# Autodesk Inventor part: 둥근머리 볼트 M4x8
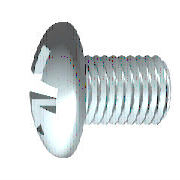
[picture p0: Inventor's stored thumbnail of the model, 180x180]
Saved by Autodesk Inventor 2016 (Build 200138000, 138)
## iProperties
Created: 2012-02
Part Number: 둥근머리 볼트 M4x8
Material: 강철, 연강
Description: 십자 오목 머리 나사
Document SubType Name: Modeling
Standard: KS B 1023
Designer: mduedu
Standards Organization: KS
Language: ko-KR
Size Designation: A  M 4 x 8 - H
Categories: <MemberInstance><Categories><Category DisplayName="조임쇠" InternalName="e4da775c-781d-43d5-af7c-5136215cf5a6" Mnemonic="FSTN"><Category DisplayName="볼트" InternalN
Density: 1 g/cm^3
Appearance: 노란색
IsCustomPart: 1
Author: mduedu
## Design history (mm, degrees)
body "Solid1"
workplane "Work Plane3"
sketch "스케치2"
  geometry: L1 (-5.374, 0)-(5.374, 0) reference; L2 (0, -5.374)-(0, 5.374) reference; L3 (0, 2.3)-(0, 0); L4 (0, 0)-(2.3, 0); L5 (0, 0)-(2.714, 2.714); L6 (0.311, 2.279)-(0.392, 0.703); L7 (2.279, 0.311)-(0.703, 0.392); L8 (0.311, -2.279)-(0.392, -0.703); L9 (2.279, -0.311)-(0.703, -0.392); L10 (-0.311, 2.279)-(-0.392, 0.703); L11 (-2.279, 0.311)-(-0.703, 0.392); L12 (-2.279, -0.311)-(-0.703, -0.392); L13 (-0.311, -2.279)-(-0.392, -0.703); A1 r 0.69 centre (0, 0) between (0.69, 0) and (0, 0.69); A2 r 2.3 centre (0, 0) between (2.3, 0) and (2.279, 0.311); A3 r 2.3 centre (0, 0) between (0.311, 2.279) and (0, 2.3); A4 r 2.3 centre (0, 0) between (2.279, 0.311) and (0.311, 2.279); A5 r 2.3 centre (0, 0) between (0, -2.3) and (0.311, -2.279); A6 r 2.3 centre (0, 0) between (0.311, -2.279) and (2.279, -0.311); A7 r 2.3 centre (0, 0) between (2.279, -0.311) and (2.3, 0); A8 r 2.3 centre (0, 0) between (-2.279, 0.311) and (-2.3, 0); A9 r 2.3 centre (0, 0) between (-0.311, 2.279) and (-2.279, 0.311); A10 r 2.3 centre (0, 0) between (0, 2.3) and (-0.311, 2.279); A11 r 2.3 centre (0, 0) between (-2.3, 0) and (-2.279, -0.311); A12 r 2.3 centre (0, 0) between (-2.279, -0.311) and (-0.311, -2.279); A13 r 2.3 centre (0, 0) between (-0.311, -2.279) and (0, -2.3); A14 r 0.805 centre (0, 0) between (0.805, 0) and (0, 0.805); A15 r 0.328 centre (0.72, 0.72) between (0.392, 0.703) and (0.703, 0.392); A16 r 0.328 centre (0.72, -0.72) between (0.703, -0.392) and (0.392, -0.703); A17 r 0.328 centre (-0.72, 0.72) between (-0.703, 0.392) and (-0.392, 0.703); A18 r 0.328 centre (-0.72, -0.72) between (-0.392, -0.703) and (-0.703, -0.392); 1 further point
  constraints: 38 point on circle, 22 end point, 19 symmetric about line, 18 centre point, 4 coincident, 3 collinear, 3 point on line, 3 tangent, 1 perpendicular, 21 other
  dimensions: "d4" = 45 deg angle of L5 L4; "d5" = 1.38 diameter of A1 (= 0.3 x SDM); "d6" = 4.6 diameter of A4 (= SDM); "d7" = 0.3115 distance from line of L6.start L3 (= 0.5 x SBR); "d14" = 1.61 diameter of A14 (= 0.35 x SDM)
extrude "슬롯" join sketch "스케치2" taper "d15" = 5 deg; stored distance "d54" = 10
revolve "절단부" stored, may be unused: angle "d56" = 90 deg
revolve "본체" stored, may be unused: angle "d18" = 90 deg
workplane "Work Plane1"
sketch "스케치1"
  geometry: L1 (8, 0)-(8, 2); L2 (8, 2)-(1.4, 2); L3 (3.962, 5.08)-(3.962, 5.08); L4 (-3.1, 0)-(-3.1, 3.729); L5 (-2.744, 2.122)-(-1.498, 1.501); L6 (-1.498, 1.501)-(-0.7, 0); L7 (-0.7, 0)-(8, 0); L8 (-5.687, 0)-(10.281, 0) reference; L9 (0, -1.016)-(0, 6.096) reference; L10 (-2.744, 2.122)-(-3.1, 2.3); L11 (-1.846, 3.839)-(-3.1, 3.729); L12 (-1.846, 3.839)-(0, 4); L13 (0, 4)-(0, 1.785); L14 (0, 1.785)-(0.971, 1.785); L15 (0.971, 1.785)-(1.4, 2); L16 (1.4, 2)-(0, 2); A1 r 6.5 centre (3.4, 0) between (-1.846, 3.839) and (-3.1, 0)
  constraints: 28 end point, 5 point on line, 4 collinear, 4 point on circle, 3 parallel, 2 perpendicular, 1 centre point, 1 horizontal, 1 tangent
  dimensions: "d1" = 4 diameter of L2 L7 (= GD); "d2" = 2.4 distance from line of L6.end L4 (= STI); "d11" = 4.6 diameter of L10.end L7 (= SDM); "d12" = 62 deg angle of L6 L7; "d13" = 26.5 deg angle of L5 L7; "d17" = 8 diameter of L12.end L7 (= KOD); "d19" = 5 deg angle of L12 L7 (= KEWI); "d20" = 3.1 distance between parallel lines of L4 L13 (= KOH); "d21" = 6.5 radius of A1 (= KR); "d23" = 3.5705 diameter of L14 L7 (= BDM); "d24" = 6.6 distance of L1.end L2.end (= GEL); "d25" = 0.42941 horizontal distance of L14.end L2.end (= GAL); "d28" = 8 distance between parallel lines of L1 L13 (= NLG)
fillet "모깎기1" dims "d29" = 1.6 (= RR)
fillet "모깎기2" dims "d16" = 0.1246 (= 0.2 x SBR)
feature "스레드" dims "d8" = 6.6 (= GEL), "d9" = 0
chamfer "모따기1" distance "d26" = 0.42941 (= -0.5 x SPD + 0.5 x GD); stored, may be unused: second distance "d27" = 0.42952 (computed from GUL), angle "d78" = 45 deg
other parameters: "GD" = 4 (= NND) [user parameter; used in 2 equation terms], "NLG" = 8 [user parameter; used in 1 equation term], "GEL" = 6.6 [user parameter; used in 2 equation terms], "KOD" = 8 [user parameter; used in 1 equation term], "KOH" = 3.1 [user parameter; used in 2 equation terms], "SDM" = 4.6 [user parameter; used in 4 equation terms], "STI" = 2.4 [user parameter; used in 1 equation term], "SBR" = 0.623 [user parameter; used in 2 equation terms], "GAL" = 0.42941 (= 0.61345 x PTC) [user parameter; used in 1 equation term], "SPD" = 3.14117 (= NND - 1.2269 x PTC) [user parameter; used in 1 equation term], "KEWI" = 5 deg [user parameter; used in 1 equation term], "d3" = -3.1 (= -KOH), "d10" = 0, "KR" = 6.5 [user parameter; used in 1 equation term], "BDM" = 3.5705 [user parameter; used in 1 equation term], "GUL" = 0.42941 (= 0.61345 x PTC) [user parameter; used in 1 equation term], "RR" = 1.6 [user parameter; used in 1 equation term], "d79" = 0, "d80" = 0, "PTC" = 0.7 [user parameter; used in 5 equation terms], "THREADDIA" = 4 [user parameter; used in 1 equation term], "TOA" = 30 deg [user parameter], "TPU" = 14.28571 (computed from PTC) [user parameter], "NND" = 4 [user parameter; used in 2 equation terms], "GD1" = 3.14117 (= THREADDIA - 1.2269 x PTC) [user parameter]
